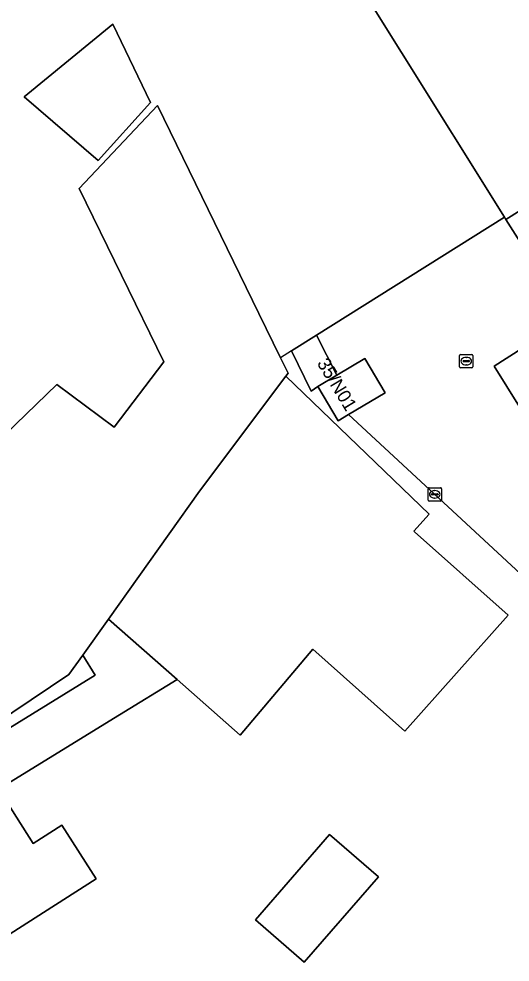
# Model space of a CAD drawing. Extents: x 158455 to 159797, y 387218 to 388672.
# Drawn here: x 158725.9 to 158762.7, y 387419.3 to 387490.1 of the extents above; entities that cross this region are included whole.
import ezdxf

# ---------------------------------------------------------------- set-up
doc = ezdxf.new("R2010")
doc.units = 0
for name, color, linetype in [('IMGEO_Erf', 7, 'Continuous'), ('IMGEO_Hek', 7, 'Continuous'), ('IMGEO_Kolk', 7, 'Continuous'), ('IMGEO_Pand', 7, 'Continuous'), ('IMGEO_Pand_nummerreeks', 7, 'Continuous'), ('IMGEO_Parkeervlak_open', 7, 'Continuous'), ('IMGEO_Rijbaan_lokaal_open', 7, 'Continuous'), ('IMGEO_Rioolput', 7, 'Continuous'), ('IMGEO_Voetpad_open', 7, 'Continuous')]:
    doc.layers.add(name, color=color, linetype=linetype)

msp = doc.modelspace()

# ---------------------------------------------------------------- linework, layer by layer
at = {"layer": 'IMGEO_Erf'}
for points in [[(158831.059, 387473.216), (158821.407, 387467.185), (158811.728, 387461.137), (158802.068, 387455.101), (158792.409, 387449.065), (158782.539, 387442.897), (158779.896, 387447.121), (158777.739, 387445.769), (158778.528, 387444.505), (158781.158, 387440.287), (158775.913, 387437.016), (158773.294, 387441.241), (158772.5, 387442.522), (158770.983, 387441.578), (158750.622, 387460.435), (158749.845, 387459.974), (158748.317, 387462.536), (158747.82, 387462.205), (158746.33, 387465.217), (158748.223, 387466.406), (158762.308, 387475.257), (158746.866, 387500)], [(158771.128, 387491.512), (158776.056, 387483.637), (158762.408, 387475.096), (158763.469, 387473.423), (158777.033, 387481.929)], [(158712.259, 387441.469), (158712.398, 387441.56), (158715.551, 387443.622), (158711.959, 387449.123), (158716.102, 387451.924), (158720.999, 387455.235), (158728.712, 387462.696), (158733.022, 387459.481), (158736.752, 387464.392), (158730.398, 387477.42), (158736.268, 387483.636), (158743.885, 387468.028), (158745.508, 387464.7)], [(158745.508, 387464.7), (158746.077, 387463.534), (158745.915, 387463.318), (158756.669, 387452.964), (158755.525, 387451.679), (158755.562, 387451.646), (158762.597, 387445.382), (158754.842, 387436.672), (158747.941, 387442.816), (158742.475, 387436.366), (158737.744, 387440.537), (158733.425, 387437.883), (158725.177, 387432.814), (158723.342, 387435.8), (158731.59, 387440.87), (158730.667, 387442.372), (158729.63, 387440.916), (158721.206, 387435.276), (158717.463, 387440.757), (158714.254, 387438.489), (158714.053, 387438.347)], [(158724.429, 387432.177), (158726.937, 387428.237), (158729.107, 387429.619), (158731.682, 387425.572), (158727.11, 387422.663), (158723.245, 387420.203)]]:
    msp.add_lwpolyline(points, dxfattribs=at)
for points in [[(158726.276, 387484.285), (158732.92, 387489.756), (158735.755, 387483.875), (158731.816, 387479.515)], [(158752.852, 387425.742), (158747.297, 387419.327), (158743.632, 387422.501), (158749.188, 387428.916)]]:
    msp.add_lwpolyline(points, close=True, dxfattribs=at)
at = {"layer": 'IMGEO_Hek'}
for points in [[(158762.308, 387475.257), (158748.223, 387466.406)], [(158746.33, 387465.217), (158745.508, 387464.7)]]:
    msp.add_lwpolyline(points, dxfattribs=at)
at = {"layer": 'IMGEO_Kolk'}
for p, q in [((158756.588, 387454.022), (158756.588, 387454.874)), ((158756.663, 387454.948), (158757.515, 387454.948)), ((158756.847, 387454.442), (158756.847, 387454.454)), ((158756.89, 387454.491), (158757.288, 387454.491)), ((158757.076, 387454.728), (158757.101, 387454.728)), ((158757.331, 387454.454), (158757.331, 387454.442)), ((158757.589, 387454.874), (158757.589, 387454.022)), ((158757.515, 387453.948), (158756.663, 387453.948)), ((158757.285, 387454.405), (158756.887, 387454.405)), ((158757.099, 387454.168), (158757.074, 387454.168))]:
    msp.add_line(p, q, dxfattribs=at)
for points in [[(158756.588, 387454.022), (158756.588, 387454.874)], [(158756.663, 387454.948), (158757.515, 387454.948)], [(158757.589, 387454.874), (158757.589, 387454.022)], [(158757.515, 387453.948), (158756.663, 387453.948)]]:
    msp.add_lwpolyline(points, dxfattribs=at)
for centre, radius, start, end in [((158756.665, 387454.872), 0.0765, 91.55205, 178.44795), ((158756.665, 387454.872), 0.0765, 91.55205, 178.44795), ((158756.887, 387454.451), 0.0403, 85.87752, 175.75265), ((158757.292, 387454.453), 0.0386, 1.73085, 96.63898), ((158757.513, 387454.872), 0.0765, 1.55205, 88.44795), ((158757.513, 387454.872), 0.0765, 1.55205, 88.44795), ((158756.665, 387454.024), 0.0765, 181.55205, 268.44795), ((158756.665, 387454.024), 0.0765, 181.55205, 268.44795), ((158756.884, 387454.441), 0.0366, 178.93798, 274.71019), ((158757.288, 387454.448), 0.043, 264.86636, 352.45326), ((158757.513, 387454.024), 0.0765, 271.55205, 358.44795), ((158757.513, 387454.024), 0.0765, 271.55205, 358.44795)]:
    msp.add_arc(centre, radius, start, end, dxfattribs=at)
for centre, major_axis, ratio, start_param, end_param in [((158757.075, 387454.448), (-0.387, 0.002), 0.722429, 4.712389, 7.853982), ((158757.1, 387454.448), (-0.39, 0.002), 0.717154, 1.570796, 4.712389)]:
    msp.add_ellipse(centre, major_axis=major_axis, ratio=ratio, start_param=start_param, end_param=end_param, dxfattribs=at)
at = {"layer": 'IMGEO_Pand'}
for points in [[(158762.408, 387475.096), (158776.056, 387483.637), (158771.128, 387491.512), (158769.42, 387494.242), (158770.54, 387494.943), (158767.794, 387499.481), (158768.61, 387500), (158769.4, 387500.503), (158769.226, 387500.781), (158768.797, 387500.506), (158761.741, 387511.827), (158745.717, 387501.841), (158746.866, 387500), (158762.308, 387475.257)], [(158735.755, 387483.875), (158732.92, 387489.756), (158726.276, 387484.285), (158731.816, 387479.515)], [(158749.734, 387463.386), (158748.317, 387462.536), (158749.845, 387459.974), (158750.622, 387460.435), (158753.375, 387462.07), (158751.828, 387464.642)], [(158755.562, 387451.646), (158755.525, 387451.679), (158756.669, 387452.964), (158745.915, 387463.318), (158739.442, 387454.686), (158732.595, 387445.077), (158737.744, 387440.537), (158742.475, 387436.366), (158747.941, 387442.816), (158754.842, 387436.672), (158762.597, 387445.382)], [(158733.425, 387437.883), (158737.744, 387440.537), (158732.595, 387445.077), (158730.667, 387442.372), (158731.59, 387440.87), (158723.342, 387435.8), (158725.177, 387432.814)], [(158721.585, 387430.367), (158717.937, 387428.045), (158717.366, 387427.682), (158717.86, 387426.905), (158717.952, 387426.053), (158718.793, 387424.727), (158719.527, 387424.281), (158720.047, 387423.462), (158720.494, 387423.746), (158722.891, 387419.978), (158723.245, 387420.203), (158727.11, 387422.663), (158731.682, 387425.572), (158729.107, 387429.619), (158726.937, 387428.237), (158724.429, 387432.177)], [(158752.852, 387425.742), (158749.188, 387428.916), (158743.632, 387422.501), (158747.297, 387419.327)]]:
    msp.add_lwpolyline(points, close=True, dxfattribs=at)
for points in [[(158745.915, 387463.318), (158746.077, 387463.534), (158745.508, 387464.7), (158743.885, 387468.028), (158736.268, 387483.636), (158730.398, 387477.42), (158736.752, 387464.392), (158733.022, 387459.481), (158728.712, 387462.696), (158720.999, 387455.235), (158716.102, 387451.924), (158711.959, 387449.123), (158715.551, 387443.622), (158712.398, 387441.56), (158712.259, 387441.469)], [(158714.053, 387438.347), (158714.254, 387438.489), (158717.463, 387440.757), (158721.206, 387435.276), (158729.63, 387440.916), (158730.667, 387442.372), (158732.595, 387445.077), (158739.442, 387454.686), (158745.915, 387463.318)]]:
    msp.add_lwpolyline(points, dxfattribs=at)
at = {"layer": 'IMGEO_Parkeervlak_open'}
msp.add_lwpolyline([(158775.233, 387451.455), (158765.697, 387466.731), (158761.538, 387464.067), (158771.06, 387448.814), (158774.476, 387450.976)], close=True, dxfattribs=at)
at = {"layer": 'IMGEO_Rijbaan_lokaal_open'}
msp.add_lwpolyline([(158777.033, 387481.929), (158763.469, 387473.423), (158762.408, 387475.096), (158762.308, 387475.257), (158748.223, 387466.406), (158749.734, 387463.386), (158751.828, 387464.642), (158753.375, 387462.07), (158750.622, 387460.435), (158770.983, 387441.578), (158772.5, 387442.522), (158773.294, 387441.241), (158778.528, 387444.505), (158777.739, 387445.769), (158779.896, 387447.121), (158777.91, 387450.295), (158775.732, 387448.927), (158774.476, 387450.976), (158771.06, 387448.814), (158761.538, 387464.067), (158765.697, 387466.731), (158767.083, 387467.619), (158766.643, 387468.328), (158817.155, 387500)], dxfattribs=at)
at = {"layer": 'IMGEO_Rioolput'}
for p, q in [((158758.949, 387464.023), (158758.949, 387464.875)), ((158759.024, 387464.949), (158759.876, 387464.949)), ((158759.208, 387464.443), (158759.208, 387464.455)), ((158759.646, 387464.406), (158759.248, 387464.406)), ((158759.251, 387464.492), (158759.649, 387464.492)), ((158759.437, 387464.729), (158759.462, 387464.729)), ((158759.692, 387464.455), (158759.692, 387464.443)), ((158759.95, 387464.875), (158759.95, 387464.023)), ((158759.876, 387463.949), (158759.024, 387463.949)), ((158759.46, 387464.169), (158759.435, 387464.169))]:
    msp.add_line(p, q, dxfattribs=at)
for points in [[(158758.949, 387464.023), (158758.949, 387464.875)], [(158759.024, 387464.949), (158759.876, 387464.949)], [(158759.95, 387464.875), (158759.95, 387464.023)], [(158759.876, 387463.949), (158759.024, 387463.949)]]:
    msp.add_lwpolyline(points, dxfattribs=at)
for centre, radius, start, end in [((158759.026, 387464.873), 0.0765, 91.55205, 178.44795), ((158759.026, 387464.873), 0.0765, 91.55205, 178.44795), ((158759.248, 387464.452), 0.0403, 85.87752, 175.75265), ((158759.245, 387464.442), 0.0366, 178.93798, 274.71019), ((158759.649, 387464.449), 0.043, 264.86636, 352.45326), ((158759.653, 387464.454), 0.0386, 1.73085, 96.63898), ((158759.874, 387464.873), 0.0765, 1.55205, 88.44795), ((158759.874, 387464.873), 0.0765, 1.55205, 88.44795), ((158759.026, 387464.025), 0.0765, 181.55205, 268.44795), ((158759.026, 387464.025), 0.0765, 181.55205, 268.44795), ((158759.874, 387464.025), 0.0765, 271.55205, 358.44795), ((158759.874, 387464.025), 0.0765, 271.55205, 358.44795)]:
    msp.add_arc(centre, radius, start, end, dxfattribs=at)
for centre, major_axis, ratio, start_param, end_param in [((158759.436, 387464.449), (-0.387, 0.002), 0.722429, 4.712389, 7.853982), ((158759.461, 387464.449), (-0.39, 0.002), 0.717154, 1.570796, 4.712389)]:
    msp.add_ellipse(centre, major_axis=major_axis, ratio=ratio, start_param=start_param, end_param=end_param, dxfattribs=at)
at = {"layer": 'IMGEO_Voetpad_open'}
msp.add_lwpolyline([(158749.734, 387463.386), (158748.223, 387466.406), (158746.33, 387465.217), (158747.82, 387462.205), (158748.317, 387462.536)], close=True, dxfattribs=at)

# ---------------------------------------------------------------- texts
at = {"layer": 'IMGEO_Pand_nummerreeks'}
msp.add_text('35/N01', height=1, rotation=301.14858, dxfattribs=at).set_placement((158748.215, 387464.295))

doc.saveas('drawing.dxf')
